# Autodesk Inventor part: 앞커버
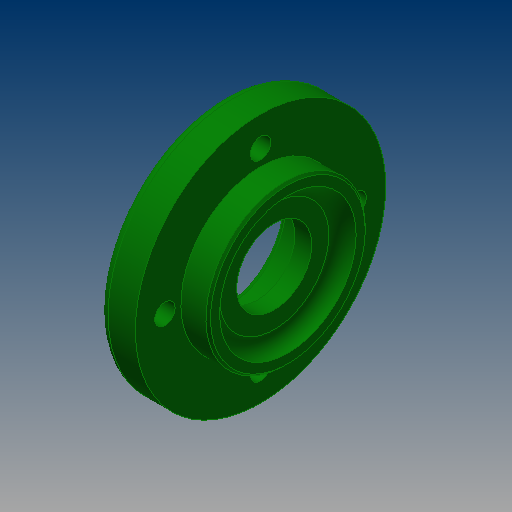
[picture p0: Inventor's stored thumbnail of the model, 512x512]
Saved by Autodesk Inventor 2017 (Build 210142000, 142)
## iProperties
Created: 2015-12
Part Number: 앞커버
Material: 알루미늄 6061
Document SubType Name: Modeling
Designer: mduedu
Density: 2.71 g/cm^3
Appearance: 진녹색
Author: mduedu
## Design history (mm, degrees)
sketch "스케치1"
  geometry: L1 (0, 0)-(14, 0); L2 (14, 0)-(14, 17.5); L3 (14, 17.5)-(8, 17.5); L4 (8, 17.5)-(8, 27.5); L5 (8, 27.5)-(0, 27.5); L6 (0, 27.5)-(0, 0)
  constraints: 12 end point, 4 parallel, 1 horizontal, 1 perpendicular
  dimensions: "d0" = 14 distance between parallel lines of L2 L6; "d2" = 8 distance of L4.end L5.end; "d3" = 55 diameter of L5 L1; "d4" = 35 diameter of L3 L1
revolve "회전1" sketch "스케치1" stored, may be unused: angle "d5" = 90 deg
hole "구멍1" diameter "d8" = 30; stored, may be unused: countersink angle "d12" = 90 deg, drill point angle "d14" = 0 deg; dims "d6" = 10, "d7" = 10, "d9" = 6, "d10" = 4, "d11" = 2, "d13" = 3
hole "구멍2" diameter "d17" = 25; stored, may be unused: countersink angle "d21" = 90 deg, drill point angle "d23" = 0 deg; dims "d15" = 10, "d16" = 10, "d18" = 6, "d19" = 4, "d20" = 2, "d22" = 7.3
hole "구멍3" diameter "d26" = 16.5; stored, may be unused: countersink angle "d30" = 90 deg, drill point angle "d32" = 0 deg; dims "d24" = 10, "d25" = 10, "d27" = 6, "d28" = 4, "d29" = 2, "d31" = 7.3
fillet "모깎기1" dims "d33" = 0.3
chamfer "모따기1" distance "d34" = 1; stored, may be unused: second distance "d35" = 2, angle "d36" = 30 deg
fillet "모깎기2" dims "d37" = 3
fillet "모깎기3" dims "d38" = 2
chamfer "모따기2" distance "d39" = 0.5; stored, may be unused: second distance "d40" = 2, angle "d41" = 45 deg
sketch "스케치2" dims "d42" = 42
  geometry: 9 further points
  constraints: 3 coincident, 2 vertical alignment, 9 other
  dimensions: "d46" = 360 deg dimension on point (0, 0) point (0, 21) (derived)
sketch "스케치3"
  geometry: 4 further points
hole "구멍4" sketch "스케치3" at (-21, 0), (0, -21), (21, 0), (0, 21) diameter "d50" = 4.5; stored, may be unused: countersink angle "d54" = 90 deg, drill point angle "d56" = 0 deg; dims "d51" = 6, "d52" = 8, "d53" = 4.6, "d55" = 8
node "솔리드1"
